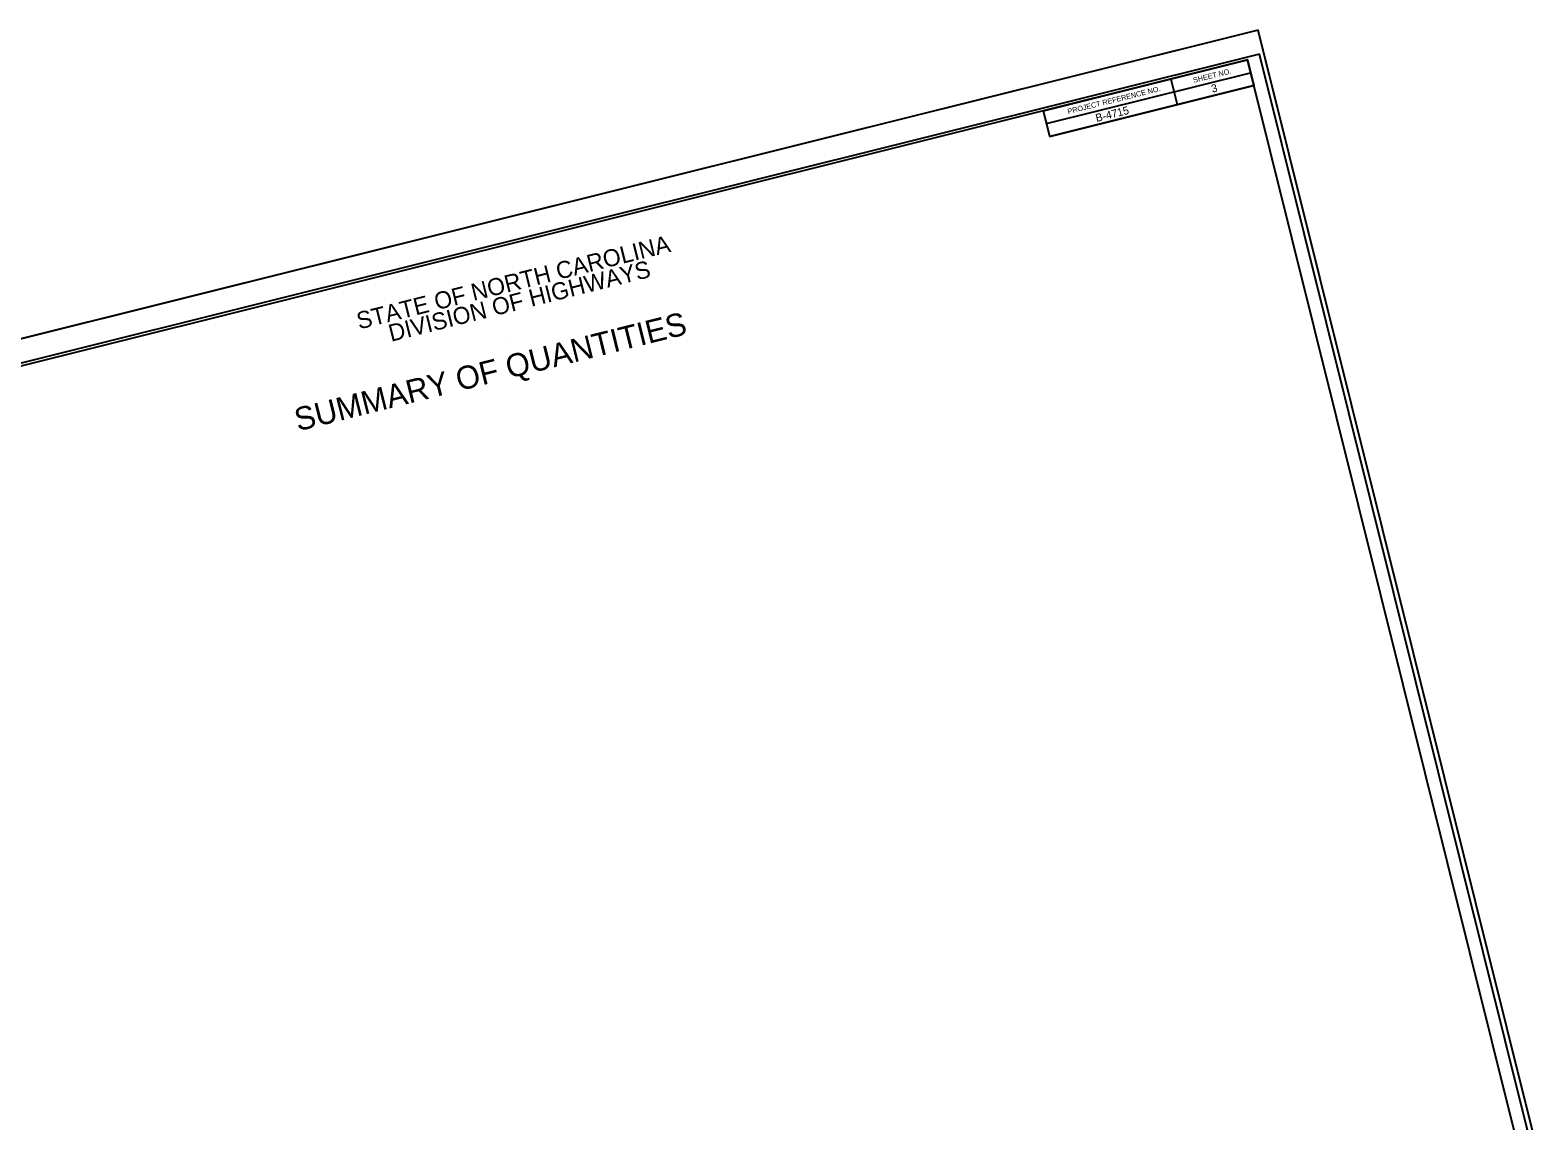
# Model space of a CAD drawing. Extents: x 1030323 to 1034123, y 654802 to 657751.
# Drawn here: x 1032422 to 1033857, y 656713 to 657751 of the extents above; entities that cross this region are included whole.
import ezdxf

# ---------------------------------------------------------------- set-up
doc = ezdxf.new("R2010")
doc.units = 0
for name, color, linetype in [('Sheet Cutting Line CELL', 7, 'Continuous'), ('Sheet Data Field CELL', 7, 'Continuous'), ('Sheet Plot Border Inside CELL', 7, 'Continuous'), ('Sheet Plot Border Outside CELL', 7, 'Continuous'), ('Sheet Summary CELL', 7, 'Continuous')]:
    doc.layers.add(name, color=color, linetype=linetype)

msp = doc.modelspace()

# ---------------------------------------------------------------- linework, layer by layer
at = {"layer": 'Sheet Cutting Line CELL'}
msp.add_line((1033590.9, 657751.2), (1031957, 657343.8), dxfattribs=at)
at = {"layer": 'Sheet Plot Border Inside CELL'}
msp.add_lwpolyline([(1033592, 657728.3), (1031975, 657325.1), (1032230.3, 656301.4), (1033847.3, 656704.5)], close=True, dxfattribs=at)
at = {"layer": 'Sheet Plot Border Outside CELL'}
msp.add_lwpolyline([(1033590.9, 657751.2), (1031957, 657343.8), (1032223.1, 656276.4), (1033857.1, 656683.8)], close=True, dxfattribs=at)
at = {"layer": 'Sheet Summary CELL'}
for p, q in [((1033389.4, 657662.2), (1033583.5, 657710.6)), ((1033392.4, 657650.1), (1033586.6, 657698.5)), ((1033507.7, 657704.6), (1033513.8, 657680.3)), ((1032873.9, 657455.1), (1032873.9, 657455.1))]:
    msp.add_line(p, q, dxfattribs=at)
for points in [[(1033580.5, 657722.8), (1032125.1, 657359.9), (1032379.1, 656341.1), (1033834.5, 656704)], [(1033386.4, 657674.4), (1033580.5, 657722.8), (1033586.6, 657698.5), (1033392.4, 657650.1)]]:
    msp.add_lwpolyline(points, close=True, dxfattribs=at)

# ---------------------------------------------------------------- texts
at = {"layer": 'Sheet Data Field CELL'}
for s, p in [('3', (1033547.2, 657691.6)), ('B-4715', (1033437, 657663.8))]:
    msp.add_text(s, height=7.5, rotation=14, dxfattribs=at).set_placement(p)
at = {"layer": 'Sheet Summary CELL'}
for s, height, p in [('SHEET NO.', 5, (1033529.5, 657701)), ('PROJECT REFERENCE NO.', 5, (1033410, 657671.3)), ('STATE OF NORTH CAROLINA', 16.25, (1032734.8, 657466.3)), ('DIVISION OF HIGHWAYS', 16.25, (1032765.2, 657454.6)), ('SUMMARY OF QUANTITIES', 21.95, (1032676.5, 657369.4))]:
    msp.add_text(s, height=height, rotation=14, dxfattribs=at).set_placement(p)

doc.saveas('drawing.dxf')
